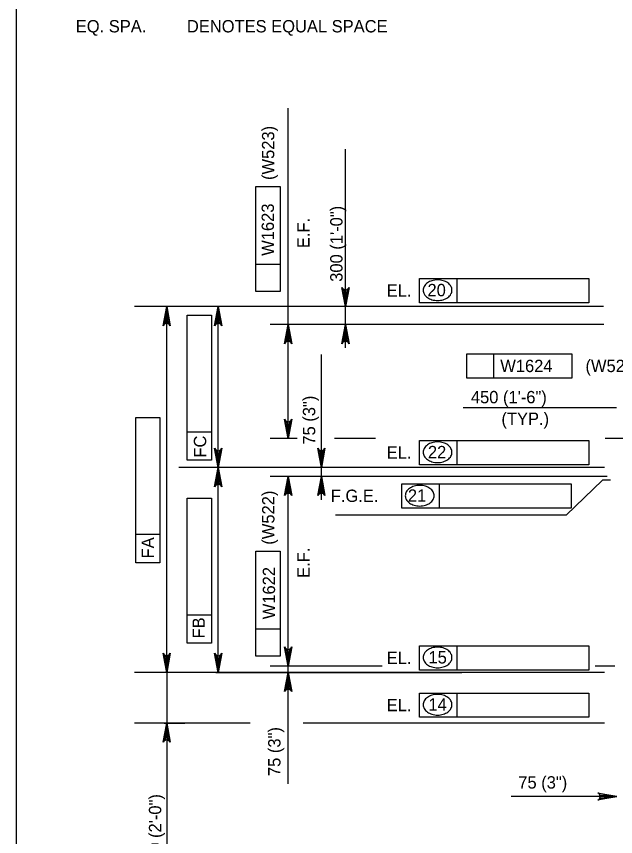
# Model space of a CAD drawing. Extents: x 634540 to 640306, y 296059 to 300275.
# Drawn here: x 639316.5 to 639462.3, y 297938.1 to 298137.5 of the extents above; entities that cross this region are included whole.
import ezdxf

# ---------------------------------------------------------------- set-up
doc = ezdxf.new("R2010")
doc.units = 0
for name, color, linetype in [('2', 7, 'Continuous'), ('3', 7, 'Continuous'), ('4', 7, 'Continuous')]:
    doc.layers.add(name, color=color, linetype=linetype)

msp = doc.modelspace()

# ---------------------------------------------------------------- linework, layer by layer
at = {"layer": '2'}
msp.add_line((639316.46, 297856.46), (639316.46, 298420.46), dxfattribs=at)
at = {"layer": '3'}
for p, q in [((639462.46, 298042.36), (639425.17, 298042.36)), ((639461.04, 298024.79), (639459.09, 298024.79))]:
    msp.add_line(p, q, dxfattribs=at)
at = {"layer": '4'}
for p, q in [((639382.59, 298037.9), (639382.59, 298115.25)), ((639396.56, 298056.95), (639396.56, 298105.22)), ((639374.7, 298070.63), (639374.7, 298096.17)), ((639374.7, 298096.17), (639380.61, 298096.17)), ((639380.61, 298096.17), (639380.61, 298070.63)), ((639380.61, 298077.22), (639374.7, 298077.22)), ((639414.57, 298073.81), (639455.78, 298073.81)), ((639414.57, 298067.9), (639414.57, 298073.81)), ((639423.74, 298067.9), (639423.74, 298073.81)), ((639455.78, 298073.81), (639455.78, 298067.9)), ((639380.61, 298070.63), (639374.7, 298070.63)), ((639459.31, 298067), (639345.19, 298067)), ((639360.57, 298067), (639348.6, 298067)), ((639425, 298067), (639361.15, 298067)), ((639455.78, 298067.9), (639414.57, 298067.9)), ((639358.04, 298029.62), (639358.04, 298064.92)), ((639358.04, 298064.92), (639363.95, 298064.92)), ((639363.95, 298064.92), (639363.95, 298029.62)), ((639353.03, 297980.99), (639353.03, 298064.04)), ((639365.57, 298030.82), (639365.57, 298064.04)), ((639459.42, 298062.63), (639378.17, 298062.63)), ((639390.67, 298020.04), (639390.67, 298055.3)), ((639426.05, 298055.49), (639451.59, 298055.49)), ((639426.05, 298049.59), (639426.05, 298055.49)), ((639432.65, 298049.59), (639432.65, 298055.49)), ((639451.59, 298055.49), (639451.59, 298049.59)), ((639451.59, 298049.59), (639426.05, 298049.59)), ((639345.49, 298004.71), (639345.49, 298040.01)), ((639345.49, 298040.01), (639351.4, 298040.01)), ((639351.4, 298040.01), (639351.4, 298004.71)), ((639363.95, 298036.47), (639358.04, 298036.47)), ((639384.81, 298034.94), (639378.17, 298034.94)), ((639403.87, 298034.94), (639393.85, 298034.94)), ((639475.72, 298034.94), (639459.69, 298034.94)), ((639414.57, 298034.43), (639455.78, 298034.43)), ((639414.57, 298028.52), (639414.57, 298034.43)), ((639423.74, 298028.52), (639423.74, 298034.43)), ((639455.78, 298034.43), (639455.78, 298028.52)), ((639363.95, 298029.62), (639358.04, 298029.62)), ((639459.59, 298027.87), (639355.96, 298027.87)), ((639431.41, 298027.87), (639361.15, 298027.87)), ((639425, 298027.87), (639361.15, 298027.87)), ((639455.78, 298028.52), (639414.57, 298028.52)), ((639365.57, 297980.99), (639365.57, 298024.92)), ((639460.2, 298025.72), (639378.17, 298025.72)), ((639410.22, 298023.86), (639451.44, 298023.86)), ((639410.22, 298017.95), (639410.22, 298023.86)), ((639419.4, 298017.95), (639419.4, 298023.86)), ((639459.09, 298024.79), (639450.25, 298016.28)), ((639451.44, 298023.86), (639451.44, 298017.95)), ((639382.59, 297978.04), (639382.59, 298022.76)), ((639358.04, 297985.14), (639358.04, 298020.44)), ((639358.04, 298020.44), (639363.95, 298020.44)), ((639363.95, 298020.44), (639363.95, 297985.14)), ((639451.44, 298017.95), (639410.22, 298017.95)), ((639450.25, 298016.28), (639394.11, 298016.28)), ((639351.4, 298011.55), (639345.49, 298011.55)), ((639374.7, 297982), (639374.7, 298007.54)), ((639374.7, 298007.54), (639380.61, 298007.54)), ((639380.61, 298007.54), (639380.61, 297982)), ((639351.4, 298004.71), (639345.49, 298004.71)), ((639363.95, 297991.99), (639358.04, 297991.99)), ((639380.61, 297988.59), (639374.7, 297988.59)), ((639363.95, 297985.14), (639358.04, 297985.14)), ((639414.57, 297984.54), (639455.78, 297984.54)), ((639414.57, 297978.63), (639414.57, 297984.54)), ((639423.74, 297978.63), (639423.74, 297984.54)), ((639455.78, 297984.54), (639455.78, 297978.63)), ((639380.61, 297982), (639374.7, 297982)), ((639405.48, 297979.58), (639378.17, 297979.58)), ((639462.07, 297979.58), (639457.29, 297979.58)), ((639459.59, 297978.04), (639345.19, 297978.04)), ((639360.57, 297978.04), (639348.6, 297978.04)), ((639353.03, 297978.04), (639353.03, 297965.74)), ((639431.41, 297978.04), (639361.15, 297978.04)), ((639364.98, 297978.04), (639424.83, 297978.04)), ((639455.78, 297978.63), (639414.57, 297978.63)), ((639382.59, 297950.99), (639382.59, 297975.09)), ((639414.57, 297973.05), (639455.78, 297973.05)), ((639414.57, 297967.14), (639414.57, 297973.05)), ((639423.74, 297967.14), (639423.74, 297973.05)), ((639455.78, 297973.05), (639455.78, 297967.14)), ((639455.78, 297967.14), (639414.57, 297967.14)), ((639373.37, 297965.74), (639345.19, 297965.74)), ((639352.43, 297965.74), (639357.46, 297965.74)), ((639459.59, 297965.74), (639386.26, 297965.74)), ((639353.03, 297962.79), (639353.03, 297927.85)), ((639456.67, 297947.89), (639436.87, 297947.89)), ((639459.63, 297947.89), (639456.67, 297947.89))]:
    msp.add_line(p, q, dxfattribs=at)
for points in [[(639396.56, 298067), (639395.68, 298071.66), (639395.93, 298071.3), (639396.25, 298071.11), (639396.56, 298071.06), (639396.87, 298071.11), (639397.18, 298071.3), (639397.43, 298071.66), (639396.56, 298067), (639397.18, 298071.3), (639396.87, 298071.11), (639396.56, 298067), (639396.56, 298071.06), (639396.25, 298071.11), (639396.56, 298067), (639395.93, 298071.3)], [(639353.03, 298067), (639353.9, 298062.34), (639353.65, 298062.69), (639353.34, 298062.88), (639353.03, 298062.93), (639352.71, 298062.88), (639352.4, 298062.69), (639352.15, 298062.34), (639353.03, 298067), (639352.4, 298062.69), (639352.71, 298062.88), (639353.03, 298067), (639353.03, 298062.93), (639353.34, 298062.88), (639353.03, 298067), (639353.65, 298062.69)], [(639365.57, 298067), (639366.45, 298062.34), (639366.2, 298062.69), (639365.89, 298062.88), (639365.57, 298062.93), (639365.26, 298062.88), (639364.95, 298062.69), (639364.7, 298062.34), (639365.57, 298067), (639364.95, 298062.69), (639365.26, 298062.88), (639365.57, 298067), (639365.57, 298062.93), (639365.89, 298062.88), (639365.57, 298067), (639366.2, 298062.69)], [(639382.59, 298062.63), (639383.47, 298057.97), (639383.22, 298058.33), (639382.91, 298058.51), (639382.59, 298058.57), (639382.28, 298058.51), (639381.97, 298058.33), (639381.72, 298057.97), (639382.59, 298062.63), (639381.97, 298058.33), (639382.28, 298058.51), (639382.59, 298062.63), (639382.59, 298058.57), (639382.91, 298058.51), (639382.59, 298062.63), (639383.22, 298058.33)], [(639396.56, 298062.63), (639397.43, 298057.97), (639397.18, 298058.33), (639396.87, 298058.51), (639396.56, 298058.57), (639396.25, 298058.51), (639395.93, 298058.33), (639395.68, 298057.97), (639396.56, 298062.63), (639395.93, 298058.33), (639396.25, 298058.51), (639396.56, 298062.63), (639396.56, 298058.57), (639396.87, 298058.51), (639396.56, 298062.63), (639397.18, 298058.33)], [(639382.59, 298034.94), (639381.72, 298039.61), (639381.97, 298039.25), (639382.28, 298039.06), (639382.59, 298039.01), (639382.91, 298039.06), (639383.22, 298039.25), (639383.47, 298039.61), (639382.59, 298034.94), (639383.22, 298039.25), (639382.91, 298039.06), (639382.59, 298034.94), (639382.59, 298039.01), (639382.28, 298039.06), (639382.59, 298034.94), (639381.97, 298039.25)], [(639365.57, 298027.87), (639364.7, 298032.53), (639364.95, 298032.17), (639365.26, 298031.99), (639365.57, 298031.93), (639365.89, 298031.99), (639366.2, 298032.17), (639366.45, 298032.53), (639365.57, 298027.87), (639366.2, 298032.17), (639365.89, 298031.99), (639365.57, 298027.87), (639365.57, 298031.93), (639365.26, 298031.99), (639365.57, 298027.87), (639364.95, 298032.17)], [(639390.67, 298027.87), (639389.79, 298032.53), (639390.04, 298032.17), (639390.36, 298031.99), (639390.67, 298031.93), (639390.98, 298031.99), (639391.29, 298032.17), (639391.54, 298032.53), (639390.67, 298027.87), (639391.29, 298032.17), (639390.98, 298031.99), (639390.67, 298027.87), (639390.67, 298031.93), (639390.36, 298031.99), (639390.67, 298027.87), (639390.04, 298032.17)], [(639365.57, 298027.87), (639366.45, 298023.21), (639366.2, 298023.57), (639365.89, 298023.75), (639365.57, 298023.81), (639365.26, 298023.75), (639364.95, 298023.57), (639364.7, 298023.21), (639365.57, 298027.87), (639364.95, 298023.57), (639365.26, 298023.75), (639365.57, 298027.87), (639365.57, 298023.81), (639365.89, 298023.75), (639365.57, 298027.87), (639366.2, 298023.57)], [(639382.59, 298025.72), (639383.47, 298021.06), (639383.22, 298021.41), (639382.91, 298021.6), (639382.59, 298021.65), (639382.28, 298021.6), (639381.97, 298021.41), (639381.72, 298021.06), (639382.59, 298025.72), (639381.97, 298021.41), (639382.28, 298021.6), (639382.59, 298025.72), (639382.59, 298021.65), (639382.91, 298021.6), (639382.59, 298025.72), (639383.22, 298021.41)], [(639390.67, 298025.72), (639391.54, 298021.06), (639391.29, 298021.41), (639390.98, 298021.6), (639390.67, 298021.65), (639390.36, 298021.6), (639390.04, 298021.41), (639389.79, 298021.06), (639390.67, 298025.72), (639390.04, 298021.41), (639390.36, 298021.6), (639390.67, 298025.72), (639390.67, 298021.65), (639390.98, 298021.6), (639390.67, 298025.72), (639391.29, 298021.41)], [(639382.59, 297979.58), (639381.72, 297984.24), (639381.97, 297983.88), (639382.28, 297983.7), (639382.59, 297983.64), (639382.91, 297983.7), (639383.22, 297983.88), (639383.47, 297984.24), (639382.59, 297979.58), (639383.22, 297983.88), (639382.91, 297983.7), (639382.59, 297979.58), (639382.59, 297983.64), (639382.28, 297983.7), (639382.59, 297979.58), (639381.97, 297983.88)], [(639353.03, 297978.04), (639352.15, 297982.7), (639352.4, 297982.34), (639352.71, 297982.16), (639353.03, 297982.1), (639353.34, 297982.16), (639353.65, 297982.34), (639353.9, 297982.7), (639353.03, 297978.04), (639353.65, 297982.34), (639353.34, 297982.16), (639353.03, 297978.04), (639353.03, 297982.1), (639352.71, 297982.16), (639353.03, 297978.04), (639352.4, 297982.34)], [(639365.57, 297978.04), (639364.7, 297982.7), (639364.95, 297982.34), (639365.26, 297982.16), (639365.57, 297982.1), (639365.89, 297982.16), (639366.2, 297982.34), (639366.45, 297982.7), (639365.57, 297978.04), (639366.2, 297982.34), (639365.89, 297982.16), (639365.57, 297978.04), (639365.57, 297982.1), (639365.26, 297982.16), (639365.57, 297978.04), (639364.95, 297982.34)], [(639382.59, 297978.04), (639383.47, 297973.38), (639383.22, 297973.74), (639382.91, 297973.92), (639382.59, 297973.98), (639382.28, 297973.92), (639381.97, 297973.74), (639381.72, 297973.38), (639382.59, 297978.04), (639381.97, 297973.74), (639382.28, 297973.92), (639382.59, 297978.04), (639382.59, 297973.98), (639382.91, 297973.92), (639382.59, 297978.04), (639383.22, 297973.74)], [(639353.03, 297965.74), (639353.9, 297961.08), (639353.65, 297961.43), (639353.34, 297961.62), (639353.03, 297961.67), (639352.71, 297961.62), (639352.4, 297961.43), (639352.15, 297961.08), (639353.03, 297965.74), (639352.4, 297961.43), (639352.71, 297961.62), (639353.03, 297965.74), (639353.03, 297961.67), (639353.34, 297961.62), (639353.03, 297965.74), (639353.65, 297961.43)], [(639462.58, 297947.89), (639457.92, 297947.02), (639458.28, 297947.27), (639458.46, 297947.58), (639458.52, 297947.89), (639458.46, 297948.21), (639458.28, 297948.52), (639457.92, 297948.77), (639462.58, 297947.89), (639458.28, 297948.52), (639458.46, 297948.21), (639462.58, 297947.89), (639458.52, 297947.89), (639458.46, 297947.58), (639462.58, 297947.89), (639458.28, 297947.27)]]:
    msp.add_lwpolyline(points, dxfattribs=at)
for points in [[(639396.07, 298069.95), (639397.05, 298069.95), (639396.56, 298067)], [(639352.53, 298064.04), (639353.52, 298064.04), (639353.03, 298067)], [(639365.08, 298064.04), (639366.07, 298064.04), (639365.57, 298067)], [(639382.1, 298059.67), (639383.09, 298059.67), (639382.59, 298062.63)], [(639396.07, 298059.67), (639397.05, 298059.67), (639396.56, 298062.63)], [(639382.1, 298037.9), (639383.09, 298037.9), (639382.59, 298034.94)], [(639365.08, 298030.82), (639366.07, 298030.82), (639365.57, 298027.87)], [(639390.17, 298030.82), (639391.16, 298030.82), (639390.67, 298027.87)], [(639365.08, 298024.92), (639366.07, 298024.92), (639365.57, 298027.87)], [(639382.1, 298022.76), (639383.09, 298022.76), (639382.59, 298025.72)], [(639390.17, 298022.76), (639391.16, 298022.76), (639390.67, 298025.72)], [(639352.53, 297980.99), (639353.52, 297980.99), (639353.03, 297978.04)], [(639365.08, 297980.99), (639366.07, 297980.99), (639365.57, 297978.04)], [(639382.1, 297982.53), (639383.09, 297982.53), (639382.59, 297979.58)], [(639382.1, 297975.09), (639383.09, 297975.09), (639382.59, 297978.04)], [(639352.53, 297962.79), (639353.52, 297962.79), (639353.03, 297965.74)], [(639459.63, 297948.38), (639459.63, 297947.4), (639462.58, 297947.89)]]:
    msp.add_lwpolyline(points, close=True, dxfattribs=at)
for centre, radius, start, end in [((639418.07, 298070.5), 2.76, 125.6316, 149.9767), ((639418.6, 298069.76), 3.66, 106.5358, 125.6316), ((639418.95, 298068.6), 4.87, 90, 106.5358), ((639418.95, 298068.6), 4.87, 73.4642, 90), ((639419.29, 298069.76), 3.66, 54.3684, 73.4642), ((639419.82, 298070.5), 2.76, 30.0233, 54.3684), ((639417.27, 298070.97), 1.83, 149.9767, 180), ((639417.27, 298070.97), 1.83, 180, 210.0233), ((639420.62, 298070.97), 1.83, 0, 30.0233), ((639420.62, 298070.97), 1.83, 329.9767, 0), ((639418.07, 298071.43), 2.76, 210.0233, 234.3684), ((639418.6, 298072.17), 3.66, 234.3684, 253.4642), ((639419.29, 298072.17), 3.66, 286.5358, 305.6316), ((639419.82, 298071.43), 2.76, 305.6316, 329.9767), ((639418.95, 298073.33), 4.87, 253.4642, 270), ((639418.95, 298073.33), 4.87, 270, 286.5358), ((639418.07, 298031.11), 2.76, 125.6316, 149.9767), ((639418.6, 298030.38), 3.66, 106.5358, 125.6316), ((639418.95, 298029.22), 4.87, 90, 106.5358), ((639418.95, 298029.22), 4.87, 73.4642, 90), ((639419.29, 298030.38), 3.66, 54.3684, 73.4642), ((639419.82, 298031.11), 2.76, 30.0233, 54.3684), ((639417.27, 298031.58), 1.83, 149.9767, 180), ((639417.27, 298031.58), 1.83, 180, 210.0233), ((639420.62, 298031.58), 1.83, 0, 30.0233), ((639420.62, 298031.58), 1.83, 329.9767, 0), ((639418.07, 298032.04), 2.76, 210.0233, 234.3684), ((639418.6, 298032.78), 3.66, 234.3684, 253.4642), ((639418.95, 298033.94), 4.87, 253.4642, 270), ((639418.95, 298033.94), 4.87, 270, 286.5358), ((639419.29, 298032.78), 3.66, 286.5358, 305.6316), ((639419.82, 298032.04), 2.76, 305.6316, 329.9767), ((639414.26, 298019.81), 3.66, 106.5358, 125.6316), ((639414.6, 298018.65), 4.87, 90, 106.5358), ((639414.6, 298018.65), 4.87, 73.4642, 90), ((639414.95, 298019.81), 3.66, 54.3684, 73.4642), ((639412.92, 298021.01), 1.83, 149.9767, 180), ((639412.92, 298021.01), 1.83, 180, 210.0233), ((639413.73, 298020.55), 2.76, 125.6316, 149.9767), ((639415.47, 298020.55), 2.76, 30.0233, 54.3684), ((639416.28, 298021.01), 1.83, 0, 30.0233), ((639416.28, 298021.01), 1.83, 329.9767, 0), ((639413.73, 298021.48), 2.76, 210.0233, 234.3684), ((639414.26, 298022.21), 3.66, 234.3684, 253.4642), ((639414.95, 298022.21), 3.66, 286.5358, 305.6316), ((639415.47, 298021.48), 2.76, 305.6316, 329.9767), ((639414.6, 298023.37), 4.87, 253.4642, 270), ((639414.6, 298023.37), 4.87, 270, 286.5358), ((639418.07, 297981.23), 2.76, 125.6316, 149.9767), ((639418.6, 297980.49), 3.66, 106.5358, 125.6316), ((639418.95, 297979.33), 4.87, 90, 106.5358), ((639418.95, 297979.33), 4.87, 73.4642, 90), ((639419.29, 297980.49), 3.66, 54.3684, 73.4642), ((639419.82, 297981.23), 2.76, 30.0233, 54.3684), ((639417.27, 297981.69), 1.83, 149.9767, 180), ((639417.27, 297981.69), 1.83, 180, 210.0233), ((639420.62, 297981.69), 1.83, 0, 30.0233), ((639420.62, 297981.69), 1.83, 329.9767, 0), ((639418.07, 297982.16), 2.76, 210.0233, 234.3684), ((639418.6, 297982.89), 3.66, 234.3684, 253.4642), ((639418.95, 297984.05), 4.87, 253.4642, 270), ((639418.95, 297984.05), 4.87, 270, 286.5358), ((639419.29, 297982.89), 3.66, 286.5358, 305.6316), ((639419.82, 297982.16), 2.76, 305.6316, 329.9767), ((639417.27, 297970.2), 1.83, 149.9767, 180), ((639418.07, 297969.74), 2.76, 125.6316, 149.9767), ((639418.6, 297969), 3.66, 106.5358, 125.6316), ((639418.95, 297967.84), 4.87, 90, 106.5358), ((639418.95, 297967.84), 4.87, 73.4642, 90), ((639419.29, 297969), 3.66, 54.3684, 73.4642), ((639419.82, 297969.74), 2.76, 30.0233, 54.3684), ((639420.62, 297970.2), 1.83, 0, 30.0233), ((639417.27, 297970.2), 1.83, 180, 210.0233), ((639418.07, 297970.67), 2.76, 210.0233, 234.3684), ((639419.82, 297970.67), 2.76, 305.6316, 329.9767), ((639420.62, 297970.2), 1.83, 329.9767, 0), ((639418.6, 297971.4), 3.66, 234.3684, 253.4642), ((639418.95, 297972.56), 4.87, 253.4642, 270), ((639418.95, 297972.56), 4.87, 270, 286.5358), ((639419.29, 297971.4), 3.66, 286.5358, 305.6316)]:
    msp.add_arc(centre, radius, start, end, dxfattribs=at)

# ---------------------------------------------------------------- texts
at = {"layer": '3'}
for s, height, p in [('450 (1\'-6")', 3.0001, (639427.05, 298043.48)), ('(TYP.)', 3, (639434.48, 298038.23))]:
    msp.add_text(s, height=height, dxfattribs=at).set_placement(p)
msp.add_text('600 (2\'-0")', height=3.0001, rotation=90, dxfattribs=at).set_placement((639351.7, 297930))
at = {"layer": '4'}
for s, height, p in [('EQ. SPA.', 3, (639330.91, 298133.64)), ('DENOTES EQUAL SPACE', 3.0001, (639357.95, 298133.64)), ('EL.', 3, (639406.55, 298069.39)), ('20', 3, (639416.49, 298069.5)), ('W1624', 3, (639434.2, 298051.07)), ('(W524)', 3, (639454.93, 298051.07)), ('EL.', 3, (639406.55, 298030)), ('22', 3, (639416.59, 298030.12)), ('F.G.E.', 3, (639392.96, 298019.49)), ('21', 3, (639411.72, 298019.55)), ('EL.', 3, (639406.55, 297980.12)), ('15', 3, (639416.73, 297980.23)), ('EL.', 3, (639406.55, 297968.63)), ('14', 3, (639416.7, 297968.74)), ('75 (3")', 3, (639438.59, 297949.82))]:
    msp.add_text(s, height=height, dxfattribs=at).set_placement(p)
for s, height, p in [('(W523)', 3, (639379.21, 298097.76)), ('W1623', 3, (639379.13, 298079.33)), ('300 (1\'-0")', 3.0001, (639395.81, 298073.01)), ('E.F.', 3, (639387.78, 298081.19)), ('75 (3")', 3, (639389.17, 298033.43)), ('FC', 3, (639362.64, 298030.27)), ('(W522)', 3, (639379.25, 298009.1)), ('FA', 3, (639349.91, 298005.77)), ('E.F.', 3, (639387.81, 298001.03)), ('W1622', 3, (639379.4, 297990.97)), ('FB', 3, (639362.31, 297986.31)), ('75 (3")', 3, (639380.72, 297952.86))]:
    msp.add_text(s, height=height, rotation=90, dxfattribs=at).set_placement(p)

doc.saveas('drawing.dxf')
